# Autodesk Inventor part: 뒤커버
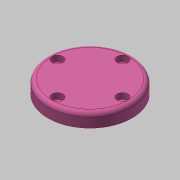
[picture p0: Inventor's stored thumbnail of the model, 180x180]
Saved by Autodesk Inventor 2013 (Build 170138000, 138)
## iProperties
Created: 2015-09
Part Number: 뒤커버
Material: 알루미늄 6061
Document SubType Name: Modeling
Designer: mduedu
Density: 1 g/cm^3
Author: mduedu
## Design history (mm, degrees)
sketch "스케치1"
  geometry: L1 (0, 7.5)-(0, -7.5); L2 (0, 7.5)-(31, 7.5); L3 (31, 7.5)-(31, -2.5); L4 (31, -2.5)-(17.5, -2.5); L5 (17.5, -2.5)-(17.5, -7.5); L6 (17.5, -7.5)-(0, -7.5); 2 further points
  constraints: 12 end point, 2 parallel, 2 perpendicular, 1 coincident, 1 horizontal, 1 midpoint, 1 vertical
  dimensions: "d0" = 15 distance of L1.start L1.end; "d1" = 62 diameter of L3 L1; "d2" = 35 diameter of L5 L1; "d3" = 10 distance of L2.end L3.end
revolve "회전1" sketch "스케치1" stored, may be unused: angle "d4" = 90 deg
fillet "모깎기2" dims "d48" = 3
sketch "스케치4" dims "d49" = 48
  geometry: 3 further points
  constraints: 2 vertical alignment, 1 coincident, 2 other
hole "구멍4" sketch "스케치4" at (0, 24) diameter "d50" = 4.5; stored, may be unused: countersink angle "d54" = 90 deg, drill point angle "d56" = 118 deg; dims "d51" = 6, "d52" = 8, "d53" = 4.4, "d55" = 8
hole "구멍5" diameter "d62" = 24; stored, may be unused: countersink angle "d66" = 90 deg, drill point angle "d68" = 0 deg; dims "d60" = 10, "d61" = 10, "d63" = 6, "d64" = 4, "d65" = 2, "d67" = 8
fillet "모깎기3" dims "d69" = 3
chamfer "모따기3" distance "d43" = 1; stored, may be unused: second distance "d44" = 2, angle "d45" = 45 deg
node "솔리드1"
pattern_circular "원형 패턴1" dims angle "d58" = 360 deg
